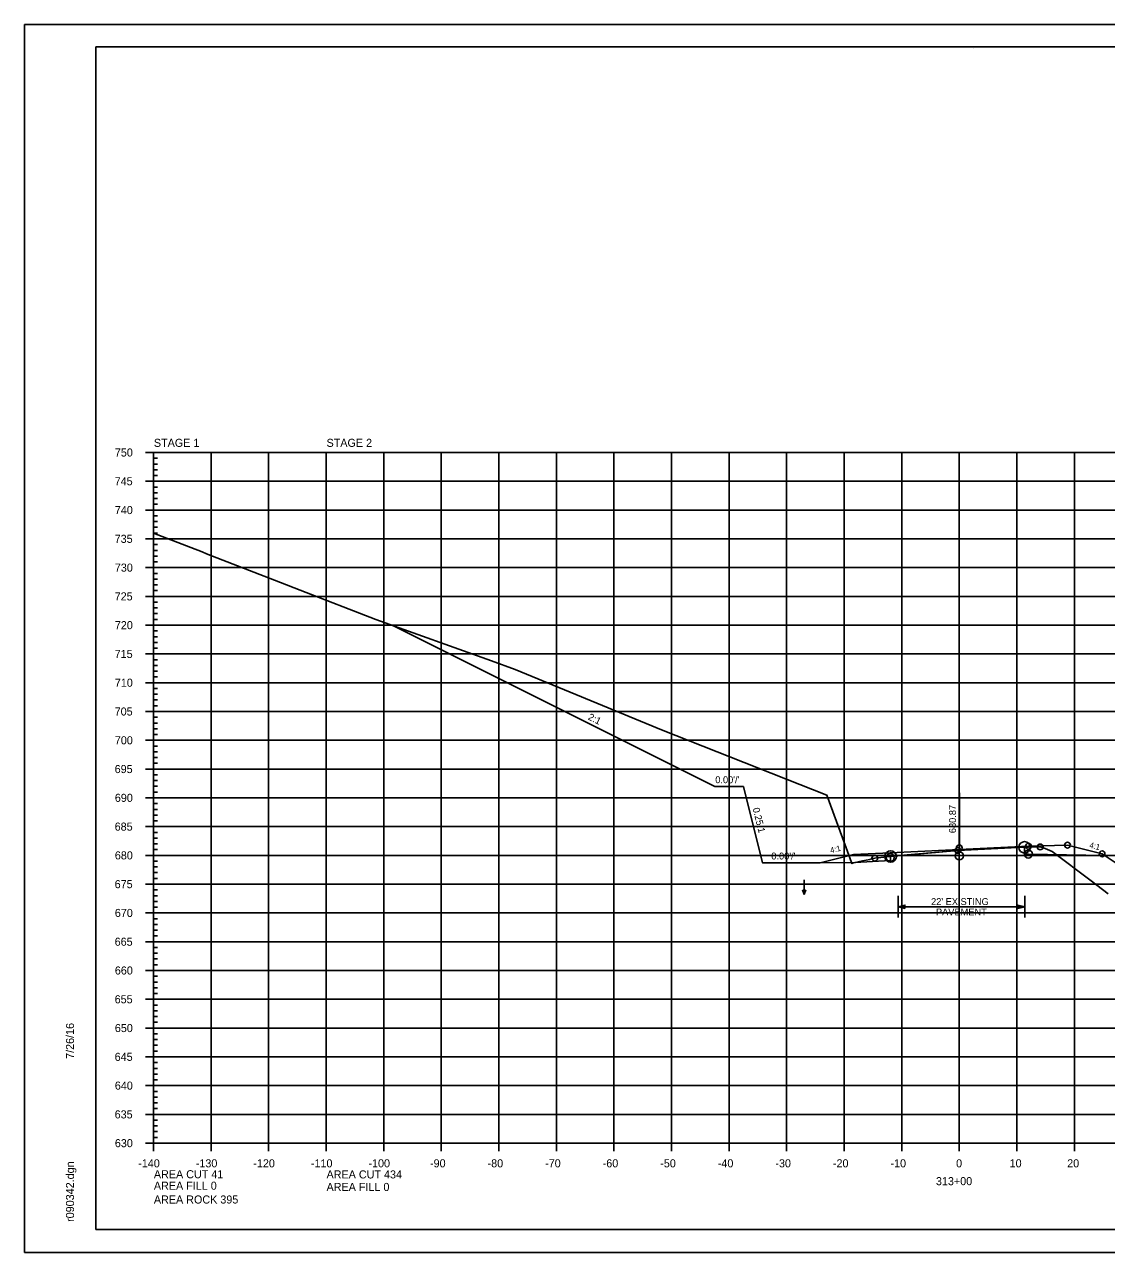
# Model space of a CAD drawing. Extents: x 1370515 to 1370849, y 383299 to 386073.
# Drawn here: x 1370515.4 to 1370703.4, y 385646.1 to 385859.5 of the extents above; entities that cross this region are included whole.
import ezdxf

# ---------------------------------------------------------------- set-up
doc = ezdxf.new("R2010")
doc.units = 0
for name, color, linetype in [('R_Alt Surface', 7, 'Continuous'), ('R_Axis', 7, 'Continuous'), ('R_Axis Annot', 7, 'Continuous'), ('R_Border', 7, 'Continuous'), ('R_Detour', 7, 'Continuous'), ('R_Exist Surface', 7, 'Continuous'), ('R_Fin Surface', 7, 'Continuous'), ('R_Grid', 7, 'Continuous'), ('R_No Plot', 7, 'Continuous'), ('R_ROW Annot', 7, 'Continuous'), ('R_Water', 7, 'Continuous'), ('R_Water Annot', 7, 'Continuous'), ('R_Xsect Elev', 7, 'Continuous'), ('R_Xsect Slope', 7, 'Continuous')]:
    doc.layers.add(name, color=color, linetype=linetype)

msp = doc.modelspace()

# ---------------------------------------------------------------- linework, layer by layer
at = {"layer": 'R_Alt Surface'}
msp.add_lwpolyline([(1370653.61, 385713.83), (1370659.63, 385713.92), (1370665.86, 385714.22), (1370665.86, 385714.94), (1370677.56, 385715.98), (1370689.14, 385716.53), (1370689.14, 385715.37), (1370689.8, 385715.35), (1370703.06, 385715.09)], dxfattribs=at)
at = {"layer": 'R_Axis'}
for p, q in [((1370536.4, 385785.13), (1370539.2, 385785.13)), ((1370537.8, 385665.13), (1370537.8, 385785.13)), ((1370537.8, 385784.13), (1370538.5, 385784.13)), ((1370537.8, 385783.13), (1370538.5, 385783.13)), ((1370537.8, 385782.13), (1370538.5, 385782.13)), ((1370537.8, 385781.13), (1370538.5, 385781.13)), ((1370536.4, 385780.13), (1370539.2, 385780.13)), ((1370537.8, 385779.13), (1370538.5, 385779.13)), ((1370537.8, 385778.13), (1370538.5, 385778.13)), ((1370537.8, 385777.13), (1370538.5, 385777.13)), ((1370536.4, 385775.13), (1370539.2, 385775.13)), ((1370537.8, 385776.13), (1370538.5, 385776.13)), ((1370537.8, 385774.13), (1370538.5, 385774.13)), ((1370537.8, 385773.13), (1370538.5, 385773.13)), ((1370537.8, 385772.13), (1370538.5, 385772.13)), ((1370536.4, 385770.13), (1370539.2, 385770.13)), ((1370537.8, 385771.13), (1370538.5, 385771.13)), ((1370537.8, 385769.13), (1370538.5, 385769.13)), ((1370537.8, 385768.13), (1370538.5, 385768.13)), ((1370537.8, 385767.13), (1370538.5, 385767.13)), ((1370537.8, 385766.13), (1370538.5, 385766.13)), ((1370536.4, 385765.13), (1370539.2, 385765.13)), ((1370537.8, 385764.13), (1370538.5, 385764.13)), ((1370537.8, 385763.13), (1370538.5, 385763.13)), ((1370537.8, 385762.13), (1370538.5, 385762.13)), ((1370536.4, 385760.13), (1370539.2, 385760.13)), ((1370537.8, 385761.13), (1370538.5, 385761.13)), ((1370537.8, 385759.13), (1370538.5, 385759.13)), ((1370537.8, 385758.13), (1370538.5, 385758.13)), ((1370537.8, 385757.13), (1370538.5, 385757.13)), ((1370536.4, 385755.13), (1370539.2, 385755.13)), ((1370537.8, 385756.13), (1370538.5, 385756.13)), ((1370537.8, 385754.13), (1370538.5, 385754.13)), ((1370537.8, 385753.13), (1370538.5, 385753.13)), ((1370537.8, 385752.13), (1370538.5, 385752.13)), ((1370537.8, 385751.13), (1370538.5, 385751.13)), ((1370536.4, 385750.13), (1370539.2, 385750.13)), ((1370537.8, 385749.13), (1370538.5, 385749.13)), ((1370537.8, 385748.13), (1370538.5, 385748.13)), ((1370537.8, 385747.13), (1370538.5, 385747.13)), ((1370536.4, 385745.13), (1370539.2, 385745.13)), ((1370537.8, 385746.13), (1370538.5, 385746.13)), ((1370537.8, 385744.13), (1370538.5, 385744.13)), ((1370537.8, 385743.13), (1370538.5, 385743.13)), ((1370537.8, 385742.13), (1370538.5, 385742.13)), ((1370536.4, 385740.13), (1370539.2, 385740.13)), ((1370537.8, 385741.13), (1370538.5, 385741.13)), ((1370537.8, 385739.13), (1370538.5, 385739.13)), ((1370537.8, 385738.13), (1370538.5, 385738.13)), ((1370537.8, 385737.13), (1370538.5, 385737.13)), ((1370537.8, 385736.13), (1370538.5, 385736.13)), ((1370536.4, 385735.13), (1370539.2, 385735.13)), ((1370537.8, 385734.13), (1370538.5, 385734.13)), ((1370537.8, 385733.13), (1370538.5, 385733.13)), ((1370537.8, 385732.13), (1370538.5, 385732.13)), ((1370536.4, 385730.13), (1370539.2, 385730.13)), ((1370537.8, 385731.13), (1370538.5, 385731.13)), ((1370537.8, 385729.13), (1370538.5, 385729.13)), ((1370537.8, 385728.13), (1370538.5, 385728.13)), ((1370536.4, 385725.13), (1370539.2, 385725.13)), ((1370537.8, 385727.13), (1370538.5, 385727.13)), ((1370537.8, 385726.13), (1370538.5, 385726.13)), ((1370537.8, 385724.13), (1370538.5, 385724.13)), ((1370537.8, 385723.13), (1370538.5, 385723.13)), ((1370537.8, 385722.13), (1370538.5, 385722.13)), ((1370537.8, 385721.13), (1370538.5, 385721.13)), ((1370536.4, 385720.13), (1370539.2, 385720.13)), ((1370537.8, 385719.13), (1370538.5, 385719.13)), ((1370537.8, 385718.13), (1370538.5, 385718.13)), ((1370537.8, 385717.13), (1370538.5, 385717.13)), ((1370536.4, 385715.13), (1370539.2, 385715.13)), ((1370537.8, 385716.13), (1370538.5, 385716.13)), ((1370537.8, 385714.13), (1370538.5, 385714.13)), ((1370537.8, 385713.13), (1370538.5, 385713.13)), ((1370536.4, 385710.13), (1370539.2, 385710.13)), ((1370537.8, 385712.13), (1370538.5, 385712.13)), ((1370537.8, 385711.13), (1370538.5, 385711.13)), ((1370537.8, 385709.13), (1370538.5, 385709.13)), ((1370537.8, 385708.13), (1370538.5, 385708.13)), ((1370537.8, 385707.13), (1370538.5, 385707.13)), ((1370537.8, 385706.13), (1370538.5, 385706.13)), ((1370536.4, 385705.13), (1370539.2, 385705.13)), ((1370537.8, 385704.13), (1370538.5, 385704.13)), ((1370537.8, 385703.13), (1370538.5, 385703.13)), ((1370537.8, 385702.13), (1370538.5, 385702.13)), ((1370536.4, 385700.13), (1370539.2, 385700.13)), ((1370537.8, 385701.13), (1370538.5, 385701.13)), ((1370537.8, 385699.13), (1370538.5, 385699.13)), ((1370537.8, 385698.13), (1370538.5, 385698.13)), ((1370537.8, 385697.13), (1370538.5, 385697.13)), ((1370537.8, 385696.13), (1370538.5, 385696.13)), ((1370536.4, 385695.13), (1370539.2, 385695.13)), ((1370537.8, 385694.13), (1370538.5, 385694.13)), ((1370537.8, 385693.13), (1370538.5, 385693.13)), ((1370537.8, 385692.13), (1370538.5, 385692.13)), ((1370537.8, 385691.13), (1370538.5, 385691.13)), ((1370536.4, 385690.13), (1370539.2, 385690.13)), ((1370537.8, 385689.13), (1370538.5, 385689.13)), ((1370537.8, 385688.13), (1370538.5, 385688.13)), ((1370537.8, 385687.13), (1370538.5, 385687.13)), ((1370536.4, 385685.13), (1370539.2, 385685.13)), ((1370537.8, 385686.13), (1370538.5, 385686.13)), ((1370537.8, 385684.13), (1370538.5, 385684.13)), ((1370537.8, 385683.13), (1370538.5, 385683.13)), ((1370537.8, 385682.13), (1370538.5, 385682.13)), ((1370537.8, 385681.13), (1370538.5, 385681.13)), ((1370536.4, 385680.13), (1370539.2, 385680.13)), ((1370537.8, 385679.13), (1370538.5, 385679.13)), ((1370537.8, 385678.13), (1370538.5, 385678.13)), ((1370537.8, 385677.13), (1370538.5, 385677.13)), ((1370537.8, 385676.13), (1370538.5, 385676.13)), ((1370536.4, 385675.13), (1370539.2, 385675.13)), ((1370537.8, 385674.13), (1370538.5, 385674.13)), ((1370537.8, 385673.13), (1370538.5, 385673.13)), ((1370537.8, 385672.13), (1370538.5, 385672.13)), ((1370536.4, 385670.13), (1370539.2, 385670.13)), ((1370537.8, 385671.13), (1370538.5, 385671.13)), ((1370537.8, 385669.13), (1370538.5, 385669.13)), ((1370537.8, 385668.13), (1370538.5, 385668.13)), ((1370537.8, 385667.13), (1370538.5, 385667.13)), ((1370537.8, 385663.73), (1370537.8, 385666.53)), ((1370537.8, 385666.13), (1370538.5, 385666.13)), ((1370547.8, 385663.73), (1370547.8, 385666.53)), ((1370557.8, 385663.73), (1370557.8, 385666.53)), ((1370567.8, 385663.73), (1370567.8, 385666.53)), ((1370577.8, 385663.73), (1370577.8, 385666.53)), ((1370587.8, 385663.73), (1370587.8, 385666.53)), ((1370597.8, 385663.73), (1370597.8, 385666.53)), ((1370607.8, 385663.73), (1370607.8, 385666.53)), ((1370617.8, 385663.73), (1370617.8, 385666.53)), ((1370627.8, 385663.73), (1370627.8, 385666.53)), ((1370637.8, 385663.73), (1370637.8, 385666.53)), ((1370647.8, 385663.73), (1370647.8, 385666.53)), ((1370657.8, 385663.73), (1370657.8, 385666.53)), ((1370667.8, 385663.73), (1370667.8, 385666.53)), ((1370677.8, 385663.73), (1370677.8, 385666.53)), ((1370687.8, 385663.73), (1370687.8, 385666.53)), ((1370697.8, 385663.73), (1370697.8, 385666.53)), ((1370536.4, 385665.13), (1370539.2, 385665.13)), ((1370537.8, 385665.13), (1370817.8, 385665.13))]:
    msp.add_line(p, q, dxfattribs=at)
at = {"layer": 'R_Border'}
for p, q in [((1370527.8, 385855.59), (1370843.98, 385855.59)), ((1370527.8, 385650.13), (1370527.8, 385855.59)), ((1370680.32, 385855.33), (1370680.32, 385855.33)), ((1370680.32, 385855.33), (1370680.32, 385855.33)), ((1370527.8, 385650.13), (1370527.8, 385650.13)), ((1370843.98, 385650.13), (1370527.8, 385650.13))]:
    msp.add_line(p, q, dxfattribs=at)
at = {"layer": 'R_Exist Surface'}
msp.add_lwpolyline([(1370537.8, 385771.11), (1370544.26, 385768.63), (1370546.24, 385767.89), (1370547.01, 385767.54), (1370559.88, 385762.56), (1370563.28, 385761.22), (1370576.41, 385756.1), (1370596.5, 385748.92), (1370600.66, 385747.44), (1370624.38, 385737.63), (1370625.1, 385737.33), (1370626.04, 385736.94), (1370654.8, 385725.57), (1370658.75, 385714.69), (1370659.14, 385713.72), (1370659.25, 385713.75), (1370660.97, 385714.17), (1370662.23, 385714.43), (1370662.29, 385714.44), (1370662.35, 385714.45), (1370663.12, 385714.63), (1370665.18, 385714.86), (1370665.86, 385714.94), (1370668.75, 385715.21), (1370677.56, 385715.98), (1370680.37, 385716.16), (1370689.14, 385716.53), (1370689.83, 385716.56), (1370691.85, 385716.59), (1370692.74, 385716.3), (1370693.96, 385715.81), (1370700.68, 385710.73), (1370703.66, 385708.46)], dxfattribs=at)
at = {"layer": 'R_Fin Surface'}
msp.add_lwpolyline([(1370579.35, 385755.05), (1370635.3, 385727.08), (1370640.3, 385727.08), (1370643.61, 385713.83), (1370653.61, 385713.83), (1370659.43, 385715.28), (1370665.8, 385715.59), (1370689.8, 385716.73), (1370696.6, 385716.9), (1370702.6, 385715.4), (1370756.63, 385679.37), (1370778.7, 385679.37), (1370792.73, 385684.05)], dxfattribs=at)
at = {"layer": 'R_Grid'}
for p, q in [((1370537.8, 385785.13), (1370817.8, 385785.13)), ((1370537.8, 385665.13), (1370537.8, 385785.13)), ((1370547.8, 385665.13), (1370547.8, 385785.13)), ((1370557.8, 385665.13), (1370557.8, 385785.13)), ((1370567.8, 385665.13), (1370567.8, 385785.13)), ((1370577.8, 385665.13), (1370577.8, 385785.13)), ((1370587.8, 385665.13), (1370587.8, 385785.13)), ((1370597.8, 385665.13), (1370597.8, 385785.13)), ((1370607.8, 385665.13), (1370607.8, 385785.13)), ((1370617.8, 385665.13), (1370617.8, 385785.13)), ((1370627.8, 385665.13), (1370627.8, 385785.13)), ((1370637.8, 385665.13), (1370637.8, 385785.13)), ((1370647.8, 385665.13), (1370647.8, 385785.13)), ((1370657.8, 385665.13), (1370657.8, 385785.13)), ((1370667.8, 385665.13), (1370667.8, 385785.13)), ((1370677.8, 385665.13), (1370677.8, 385785.13)), ((1370687.8, 385665.13), (1370687.8, 385785.13)), ((1370697.8, 385665.13), (1370697.8, 385785.13)), ((1370537.8, 385780.13), (1370817.8, 385780.13)), ((1370537.8, 385775.13), (1370817.8, 385775.13)), ((1370537.8, 385770.13), (1370817.8, 385770.13)), ((1370537.8, 385765.13), (1370817.8, 385765.13)), ((1370537.8, 385760.13), (1370817.8, 385760.13)), ((1370537.8, 385755.13), (1370817.8, 385755.13)), ((1370537.8, 385750.13), (1370817.8, 385750.13)), ((1370537.8, 385745.13), (1370817.8, 385745.13)), ((1370537.8, 385740.13), (1370817.8, 385740.13)), ((1370537.8, 385735.13), (1370817.8, 385735.13)), ((1370537.8, 385730.13), (1370817.8, 385730.13)), ((1370537.8, 385725.13), (1370817.8, 385725.13)), ((1370537.8, 385720.13), (1370817.8, 385720.13)), ((1370537.8, 385715.13), (1370817.8, 385715.13)), ((1370537.8, 385710.13), (1370817.8, 385710.13)), ((1370537.8, 385705.13), (1370817.8, 385705.13)), ((1370537.8, 385700.13), (1370817.8, 385700.13)), ((1370537.8, 385695.13), (1370817.8, 385695.13)), ((1370537.8, 385690.13), (1370817.8, 385690.13)), ((1370537.8, 385685.13), (1370817.8, 385685.13)), ((1370537.8, 385680.13), (1370817.8, 385680.13)), ((1370537.8, 385675.13), (1370817.8, 385675.13)), ((1370537.8, 385670.13), (1370817.8, 385670.13)), ((1370537.8, 385665.13), (1370817.8, 385665.13))]:
    msp.add_line(p, q, dxfattribs=at)
at = {"layer": 'R_No Plot'}
for p, q in [((1370515.4, 385859.48), (1370848.73, 385859.48)), ((1370515.4, 385646.15), (1370848.73, 385646.15))]:
    msp.add_line(p, q, dxfattribs=at)
for points in [[(1370515.39, 385859.48), (1370848.73, 385859.48), (1370848.73, 385646.14), (1370515.39, 385646.14)], [(1370761.72, 385855.59), (1370761.72, 385845.71), (1370797.45, 385845.71), (1370797.45, 385842.79), (1370820.65, 385842.79), (1370820.65, 385819.57), (1370843.98, 385819.57), (1370843.98, 385650.13), (1370527.8, 385650.13), (1370527.8, 385855.59)]]:
    msp.add_lwpolyline(points, close=True, dxfattribs=at)
for centre, radius in [((1370677.8, 385716.42), 0.5), ((1370689.14, 385716.53), 1), ((1370689.8, 385716.73), 0.5), ((1370691.85, 385716.59), 0.5), ((1370696.6, 385716.9), 0.5), ((1370663.12, 385714.63), 0.5), ((1370665.86, 385714.94), 1), ((1370665.8, 385714.75), 0.7), ((1370677.56, 385715.98), 0.5), ((1370677.8, 385715.05), 0.7), ((1370677.8, 385715.05), 0.7), ((1370689.8, 385715.35), 0.7), ((1370702.6, 385715.4), 0.5)]:
    msp.add_circle(centre, radius, dxfattribs=at)
at = {"layer": 'R_ROW Annot'}
for p, q in [((1370667.16, 385704.31), (1370667.16, 385708.08)), ((1370689.16, 385704.31), (1370689.16, 385708.08)), ((1370689.16, 385706.2), (1370667.16, 385706.2))]:
    msp.add_line(p, q, dxfattribs=at)
for points in [[(1370668.36, 385705.9), (1370667.16, 385706.2), (1370668.36, 385706.5)], [(1370687.96, 385706.5), (1370689.16, 385706.2), (1370687.96, 385705.9)]]:
    msp.add_lwpolyline(points, close=True, dxfattribs=at)
at = {"layer": 'R_Water'}
msp.add_line((1370653.63, 385713.82), (1370659.65, 385713.91), dxfattribs=at)
at = {"layer": 'R_Water Annot'}
for p, q in [((1370650.85, 385710.86), (1370650.85, 385708.35)), ((1370650.85, 385708.35), (1370650.57, 385709.12)), ((1370650.85, 385708.35), (1370651.13, 385709.12))]:
    msp.add_line(p, q, dxfattribs=at)
at = {"layer": 'R_Xsect Elev'}
for p, q in [((1370677.8, 385715.05), (1370677.8, 385725.05)), ((1370677.82, 385715.99), (1370677.82, 385725.99))]:
    msp.add_line(p, q, dxfattribs=at)

# ---------------------------------------------------------------- texts
at = {"layer": 'R_Axis'}
msp.add_text('-', height=0.0001, dxfattribs=at).set_placement((1370537.8, 385665.13))
at = {"layer": 'R_Axis Annot'}
for s, p in [('STAGE 1', (1370537.86, 385786.11)), ('STAGE 2', (1370567.86, 385786.11)), ('750', (1370531.08, 385784.43)), ('745', (1370531.05, 385779.43)), ('740', (1370531.08, 385774.43)), ('735', (1370531.05, 385769.43)), ('730', (1370531.08, 385764.43)), ('725', (1370531.05, 385759.43)), ('720', (1370531.08, 385754.43)), ('715', (1370531.05, 385749.43)), ('710', (1370531.08, 385744.43)), ('705', (1370531.05, 385739.43)), ('700', (1370531.08, 385734.43)), ('695', (1370531.05, 385729.43)), ('690', (1370531.08, 385724.43)), ('685', (1370531.05, 385719.43)), ('680', (1370531.08, 385714.43)), ('675', (1370531.05, 385709.43)), ('670', (1370531.08, 385704.43)), ('665', (1370531.05, 385699.43)), ('660', (1370531.08, 385694.43)), ('655', (1370531.05, 385689.43)), ('650', (1370531.08, 385684.43)), ('645', (1370531.05, 385679.43)), ('640', (1370531.08, 385674.43)), ('635', (1370531.05, 385669.43)), ('630', (1370531.08, 385664.43)), ('-140', (1370535.14, 385660.93)), ('-130', (1370545.14, 385660.93)), ('-120', (1370555.14, 385660.93)), ('-110', (1370565.14, 385660.93)), ('-100', (1370575.14, 385660.93)), ('-90', (1370585.84, 385660.93)), ('-80', (1370595.84, 385660.93)), ('-70', (1370605.84, 385660.93)), ('-60', (1370615.84, 385660.93)), ('-50', (1370625.84, 385660.93)), ('-40', (1370635.84, 385660.93)), ('-30', (1370645.84, 385660.93)), ('-20', (1370655.84, 385660.93)), ('-10', (1370665.84, 385660.93)), ('0', (1370677.24, 385660.93)), ('10', (1370686.54, 385660.93)), ('20', (1370696.54, 385660.93)), ('AREA CUT 41', (1370537.86, 385659.03)), ('AREA CUT 434', (1370567.86, 385659)), ('313+00', (1370673.74, 385657.83)), ('AREA FILL 0', (1370537.86, 385657.04)), ('AREA FILL 0', (1370567.86, 385656.82)), ('AREA ROCK 395', (1370537.86, 385654.64))]:
    msp.add_text(s, height=1.4, dxfattribs=at).set_placement(p)
at = {"layer": 'R_Border'}
for s, p in [('7/26/16', (1370523.99, 385679.77)), ('r090342.dgn', (1370523.99, 385651.45))]:
    msp.add_text(s, height=1.4, rotation=90, dxfattribs=at).set_placement(p)
at = {"layer": 'R_Detour'}
msp.add_text('2:1', height=1.2, rotation=333.4349, dxfattribs=at).set_placement((1370613.19, 385738.8))
at = {"layer": 'R_Fin Surface'}
for p in [(1370635.4, 385727.67), (1370645.14, 385714.42)]:
    msp.add_text("0.00'/'", height=1.2, dxfattribs=at).set_placement(p)
msp.add_text('0.25:1', height=1.2, rotation=284.0362, dxfattribs=at).set_placement((1370641.88, 385723.27))
at = {"layer": 'R_No Plot'}
for p in [(1370546.19, 385767.84), (1370576.37, 385756.05), (1370600.61, 385747.39), (1370625.06, 385737.28), (1370654.76, 385725.52), (1370662.25, 385714.39), (1370693.92, 385715.76), (1370659.1, 385713.67), (1370660.93, 385714.12)]:
    msp.add_text('+', height=0.1, dxfattribs=at).set_placement(p)
at = {"layer": 'R_ROW Annot'}
for s, p in [("22' EXISTING", (1370672.89, 385706.5)), ('PAVEMENT', (1370673.74, 385704.7))]:
    msp.add_text(s, height=1.2, dxfattribs=at).set_placement(p)
at = {"layer": 'R_Xsect Elev'}
msp.add_text('680.87', height=1.2, rotation=90, dxfattribs=at).set_placement((1370677.22, 385718.99))
at = {"layer": 'R_Xsect Slope'}
for rotation, p in [(14.0362, (1370655.49, 385715.49)), (345.9638, (1370700.32, 385716.48))]:
    msp.add_text('4:1', height=1, rotation=rotation, dxfattribs=at).set_placement(p)

doc.saveas('drawing.dxf')
